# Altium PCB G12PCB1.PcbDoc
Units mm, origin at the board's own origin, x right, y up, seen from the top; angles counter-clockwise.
Board outline 41 x 76.01 mm, 2 copper layers (Top Layer, Bottom Layer); 30 components, 21 nets, 144 pads, 45 vias.
Unrouted connection lines stored in the file: 2.
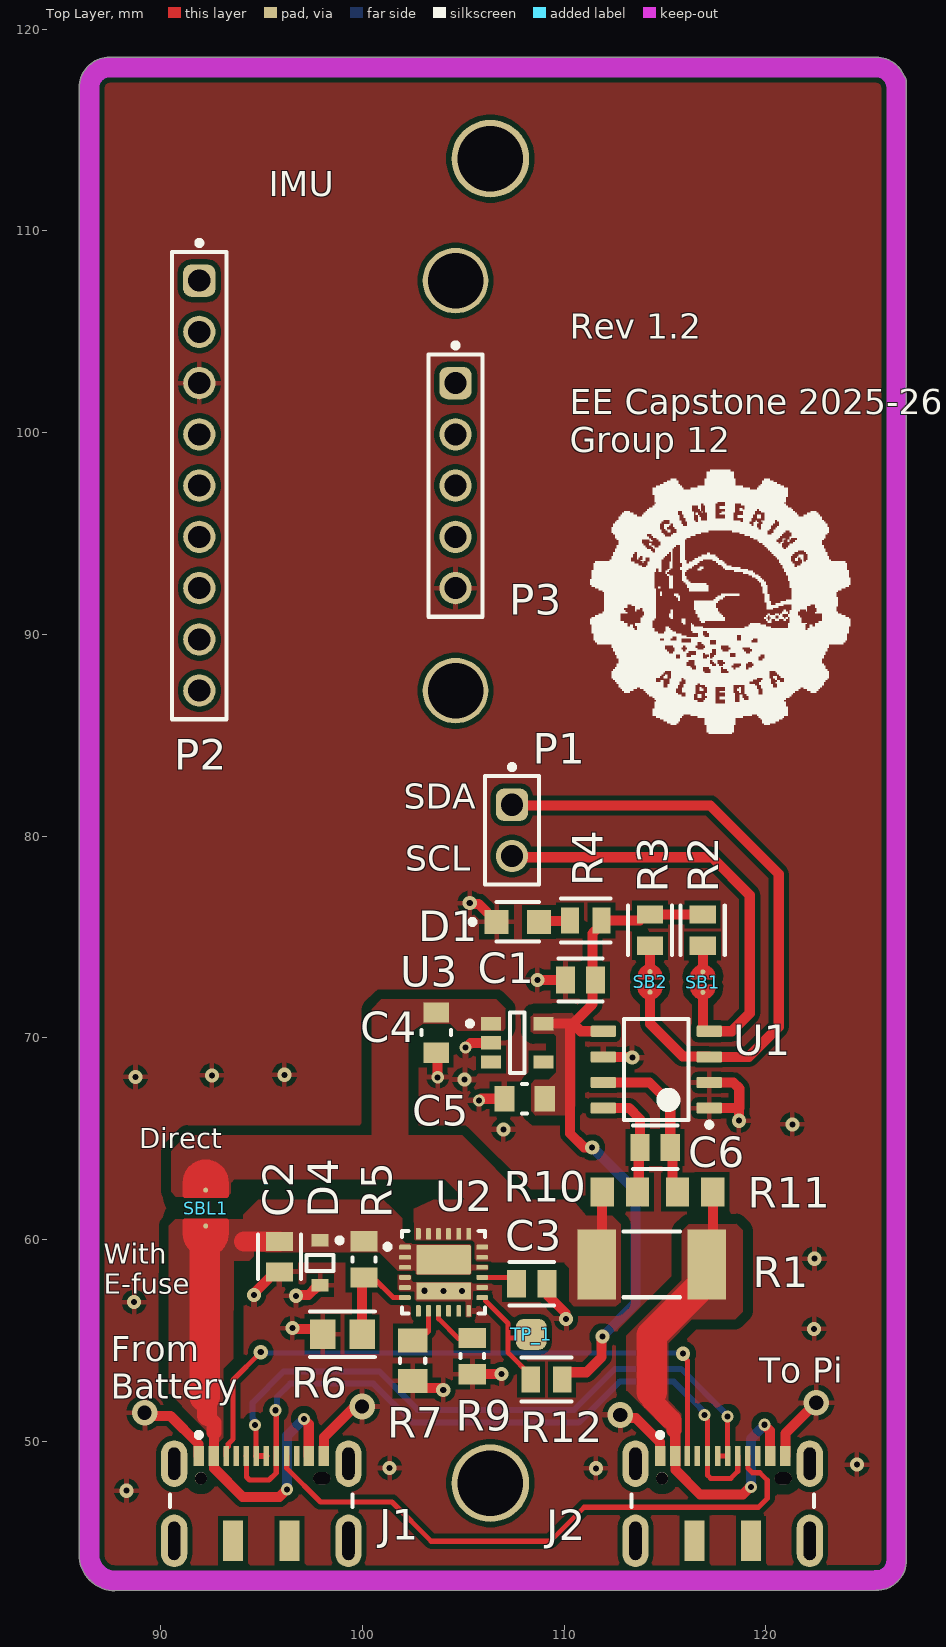
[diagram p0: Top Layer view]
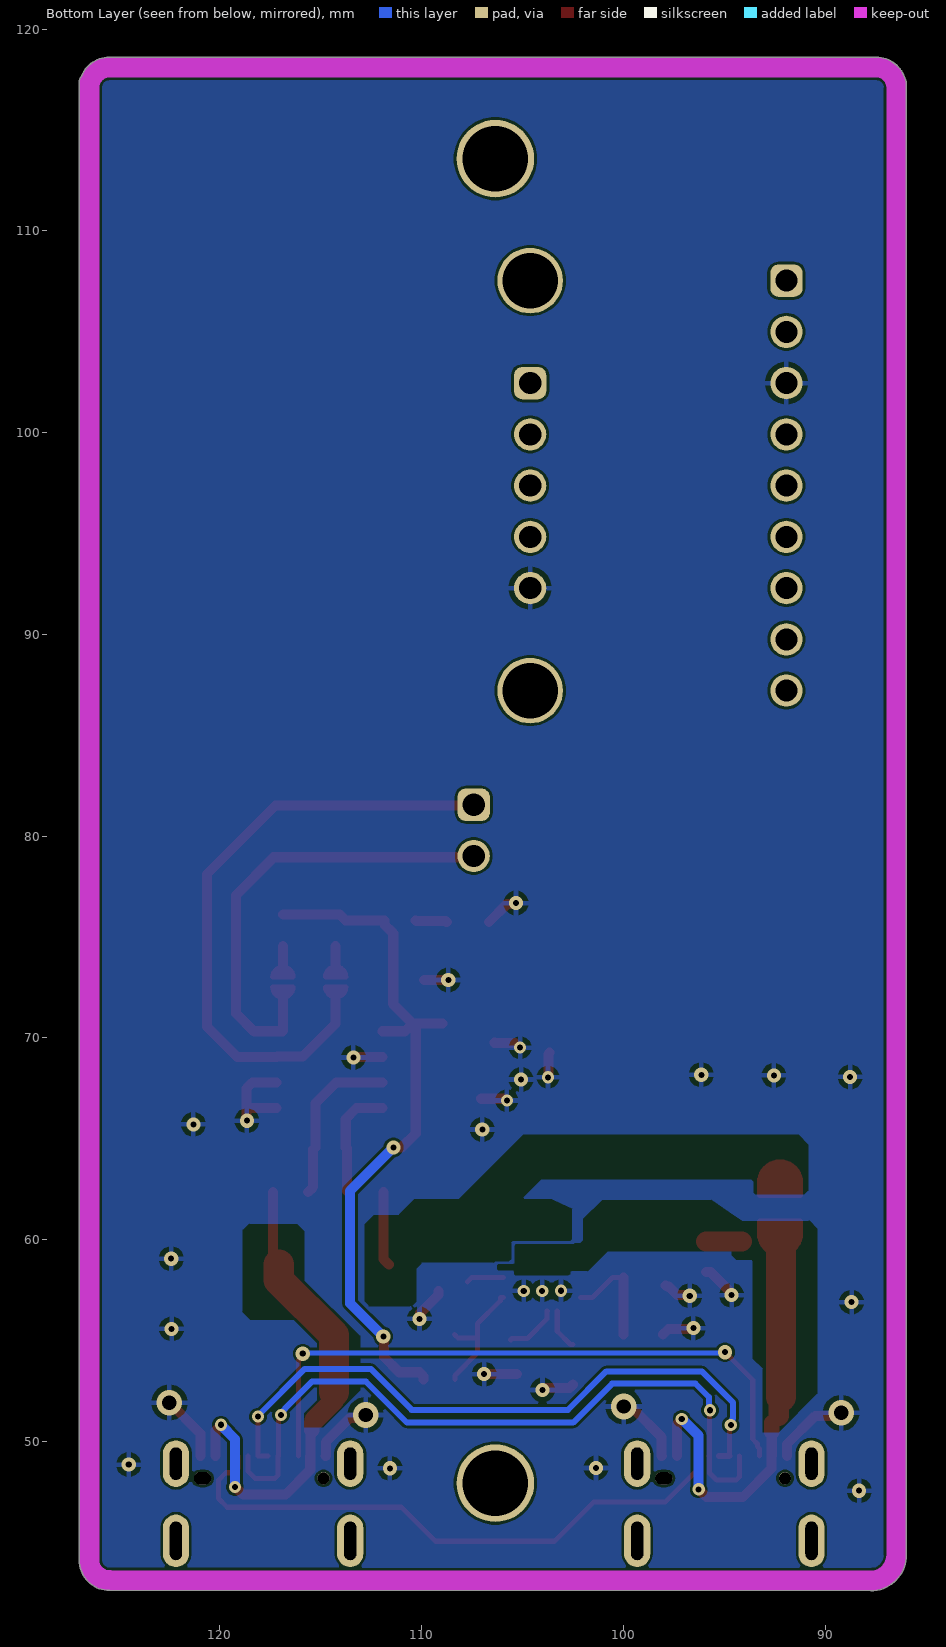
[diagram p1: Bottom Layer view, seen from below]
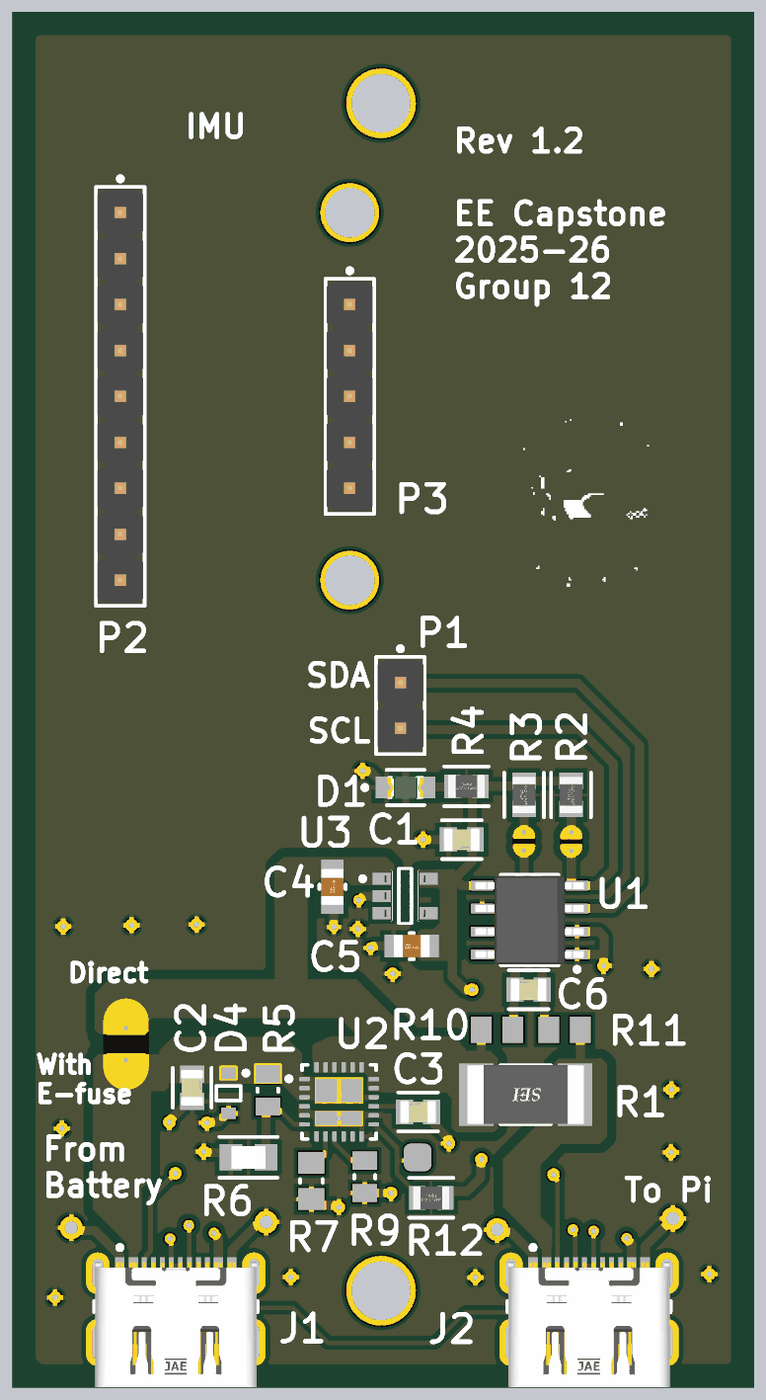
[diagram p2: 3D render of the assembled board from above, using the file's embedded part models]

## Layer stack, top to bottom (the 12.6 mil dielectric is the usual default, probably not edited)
Top Solder: solder mask 0.0102, Solder Resist, Dk 3.5
Top Layer: signal copper 0.0356
Dielectric 1: dielectric 0.32, FR-4, Dk 4.8
Bottom Layer: signal copper 0.0356
Bottom Solder: solder mask 0.0102, Solder Resist, Dk 3.5

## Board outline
85.969,44.367 85.969,117.105 cw(c87.469,117.105) 87.469,118.605 125.469,118.605 cw(c125.469,117.105) 126.853,117.684 cw(c126.469,117.363) 126.969,117.363 126.969,44.113 cw(c125.469,44.113) 125.469,42.613 87.739,42.597 cw(c87.739,44.367)

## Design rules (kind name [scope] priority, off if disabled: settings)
BoardOutlineClearance [All] p1: gap=0.5 ignorepadtopadclearanceinfootprint=FALSE
Clearance Clearance_8 [InComponent('SBL1') vs InNamedPolygon('GND_L01_P029')] p1: gap=1 ignorepadtopadclearanceinfootprint=FALSE
Clearance Clearance_7 [(HasFootprint('Solder Bridge (Large)')) vs InNet('GND')] p2: gap=0.75 ignorepadtopadclearanceinfootprint=FALSE
Clearance Clearance_6 [InNamedPolygon('+5_IN_L02_P000') vs InNamedPolygon('GND_L02_P028')] p3: gap=0.5 ignorepadtopadclearanceinfootprint=FALSE
Clearance Clearance_5 [InNamedPolygon('GND_L01_P029')] p4: gap=0.254 ignorepadtopadclearanceinfootprint=FALSE except(0.5: Poly-Poly Poly-Region Poly-Text Poly-Hole)
Clearance Clearance_4 [InNamedPolygon('NONET_L02_P027') vs IsNamedPolygon('GND_L01_P029')] p5: gap=0.5 ignorepadtopadclearanceinfootprint=FALSE
Clearance Clearance_3 [InNamedPolygon('GND_L01_P029')] p6: gap=0.2 ignorepadtopadclearanceinfootprint=FALSE
Clearance Clearance_2 [IsNamedPolygon('GND_L01_P029')] p7: gap=0.2 ignorepadtopadclearanceinfootprint=FALSE
Clearance Clearance_1 [All] p8: gap=0.127 ignorepadtopadclearanceinfootprint=TRUE
Clearance [All] p9 off: gap=0.2 ignorepadtopadclearanceinfootprint=FALSE
HoleSize HoleSize_1 [All] p1: absolutevalues=TRUE maxlimit=5 minlimit=0.15 maxpercent=80.000 minpercent=20.000
HoleSize [All] p2 off: absolutevalues=TRUE maxlimit=2.54 minlimit=0.025 maxpercent=80.000 minpercent=20.000
MinimumAnnularRing [All] p1: minimumring=0.1
MinimumSolderMaskSliver MinimumSolderMaskSliver_1 [All] p1: minsoldermaskwidth=0.2
MinimumSolderMaskSliver [All] p2: minsoldermaskwidth=0.254
PolygonConnect PolygonConnect_4 [All vs IsNamedPolygon('+5_IN_L02_P000')] p1: connectstyle=Relief reliefconductorwidth=0.254 reliefentries=4 polygonreliefangle="90 Angle" airgapwidth=0.254
PolygonConnect PolygonConnect_3 [IsNamedPolygon('GND_L01_P029')] p2: connectstyle=Relief reliefconductorwidth=0.254 reliefentries=4 polygonreliefangle="90 Angle" airgapwidth=0.254
PolygonConnect PolygonConnect_2 [All vs IsNamedPolygon('GND_L02_P028')] p3: connectstyle=Relief reliefconductorwidth=0.254 reliefentries=4 polygonreliefangle="90 Angle" airgapwidth=0.254
PolygonConnect "E-fuse In" [All vs IsNamedPolygon('+5_IN_L01_P006')] p4 off: thpad.connectstyle=NoConnect thpad.reliefconductorwidth=0.254 thpad.reliefentries=4 thpad.polygonreliefangle="90 Angle" thpad.airgapwidth=0.254 smdpad.connectstyle=NoConnect smdpad.reliefconductorwidth=0.254 smdpad.reliefentries=4 smdpad.polygonreliefangle="90 Angle" smdpad.airgapwidth=0.254 via.connectstyle=Relief via.reliefconductorwidth=0.254 via.reliefentries=4 via.polygonreliefangle="90 Angle" via.airgapwidth=0.254
PolygonConnect PolygonConnect_1 [All vs IsNamedPolygon('NONET_L01_P008')] p5 off: thpad.connectstyle=Direct thpad.reliefconductorwidth=0.254 thpad.reliefentries=4 thpad.polygonreliefangle="90 Angle" thpad.airgapwidth=0.254 smdpad.connectstyle=Direct smdpad.reliefconductorwidth=0.254 smdpad.reliefentries=4 smdpad.polygonreliefangle="90 Angle" smdpad.airgapwidth=0.254 via.connectstyle=Relief via.reliefconductorwidth=0.254 via.reliefentries=4 via.polygonreliefangle="90 Angle" via.airgapwidth=0.254
PolygonConnect [All] p6: connectstyle=Direct reliefconductorwidth=0.254 reliefentries=4 polygonreliefangle="90 Angle" airgapwidth=0.254
RoutingVias RoutingVias_2 [All] p1: holewidth=0.711 width=1.27 viastyle="Through Hole" minholewidth=0.15 minwidth=0.25 maxholewidth=0.711 maxwidth=1.27
RoutingVias RoutingVias_1 [All] p2: holewidth=0.711 width=1.27 viastyle="Through Hole" minholewidth=0.3 minwidth=0.6 maxholewidth=0.711 maxwidth=1.27
RoutingVias [All] p3: holewidth=0.711 width=1.27 viastyle="Through Hole" minholewidth=0.711 minwidth=1.27 maxholewidth=0.711 maxwidth=1.27
SilkToSolderMaskClearance [IsPad] p1: minsilkscreentomaskgap=0.2 clearancetoexposedcopper=TRUE
SolderMaskExpansion [All] p1: expansion=0.102 istentingtop=FALSE
SupplyNets "Schematic Supply Nets_4" [InNet('+3V3')] p1: voltage=0.000
SupplyNets "Schematic Supply Nets_2" [InNet('+5 OUT')] p2: voltage=0.000
SupplyNets "Schematic Supply Nets_3" [InNet('+5 IN')] p3: voltage=0.000
SupplyNets "Schematic Supply Nets_1" [InNet('+5')] p4: voltage=0.000
SupplyNets "Schematic Supply Nets" [InNet('GND')] p5: voltage=0.000
Width Width_1 [All] p1: maxlimit=2 minlimit=0.127 preferedwidth=0.3
Width [All] p2 off: maxlimit=1 minlimit=0.254 preferedwidth=0.254 minimp=50.000000 maximp=50.000000 favimp=50.000000
27 further rules are at their usual default settings.

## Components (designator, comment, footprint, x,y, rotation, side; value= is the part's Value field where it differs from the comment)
C1 "C0805C104K5RACTU" FP-C0805C-DN-MFG 110.815,72.87 r180 top value="0.10 μF"
C2 "C0805C104K5RACTU" FP-C0805C-DN-MFG 95.892,59.153 r270 top value="0.10 μF"
C3 "C0805C223J1RACAUTO" FP-C0805C-DN-MFG 108.398,57.817 r0 top value="22,000 pF"
C4 "08051C105K4T2A" FP-0805-L_2_01_0_2-W_1_25-MFG 103.659,70.261 r270 top
C5 "08051C105K4T2A" FP-0805-L_2_01_0_2-W_1_25-MFG 108.042,66.982 r180 top
C6 "C0805C104K5RACTU" FP-C0805C-DN-MFG 114.511,64.572 r0 top value="0.10 μF"
D1 "APHCM2012CGCK-F01" FP-APHCM2012CGCK-F01-MFG 107.705,75.749 r0 top
D4 "SD05T1G" ONSC-SOD-323-2-477-02_G_V 97.907,58.849 r270 top
J1 "DX07S016JA1R1500" FP-DX07S016JA1R1500-MFG 94.994,46.07 r0 top
J2 "DX07S016JA1R1500" FP-DX07S016JA1R1500-MFG 117.858,46.07 r0 top
P1 "61300211121" 61300211121 107.418,80.284 r270 top
P2 "61300911121" 61300911121 91.919,97.373 r270 top
P3 "61300511121" 61300511121 104.619,97.373 r270 top
R1 "CSRF2512FT10L0" FP-CSRF2512-IPC_B 114.352,58.769 r180 top
R2 "CRGCQ0805F4K7" FP-CRGCQ0805-IPC_C 116.864,75.339 r90 top value=4.7KΩ
R3 "CRGCQ0805F4K7" FP-CRGCQ0805-IPC_C 114.259,75.339 r90 top value=4.7KΩ
R4 "CRGCQ0805F4K7" FP-CRGCQ0805-IPC_C 111.074,75.817 r0 top value=4.7KΩ
R5 "RV0805FR-071ML" RESC2013X60X35NL10T20 100.088,59.018 r90 top
R6 "CR0805-FX-4323ELF" FP-CR0805-IPC_A 99.01,55.309 r0 top
R7 "RC0805FR-07357RL" RESC2013X60X35ML10T20 102.493,53.998 r90 top
R9 "RC0805FR-07316RL" RESC2013X60X35NL10T20 105.446,54.23 r270 top
R10 "ERJ-6ENF10R0V" RESC2013X70X40NL20T20 112.763,62.358 r180 top
R11 "ERJ-6ENF10R0V" RESC2013X70X40NL20T20 116.497,62.358 r0 top
R12 "CRGCQ0805J10K" FP-CRGCQ0805-IPC_C 109.128,53.069 r0 top value=10KΩ
SB1 "Solder Bridge" "Solder Bridge"#1 116.877,72.764 r270 top
SB2 "Solder Bridge" "Solder Bridge"#2 114.259,72.775 r270 top
SBL1 "Solder Bridge (Large)" "Solder Bridge (Large)" 92.236,61.564 r270 top
TP_1 "TP_1" "Test Pad" 108.375,55.303 r90 top
U1 "INA219AIDR" D0008A_L 114.57,68.425 r180 top
U3 "MIC5504-3.3YM5-TR" FP-SOT23-5LD-PL-1-MFG 107.679,69.757 r0 top

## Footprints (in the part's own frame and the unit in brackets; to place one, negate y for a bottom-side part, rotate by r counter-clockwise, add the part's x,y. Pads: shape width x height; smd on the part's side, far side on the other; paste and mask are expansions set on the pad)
61300211121 [mm] "Pin Header, pitch 2.54 mm, THT, Vertical, single row, 2p"
  rrect50% 1.6x1.6 hole 1.1: 1(-1.27,0)
  round 1.6 hole 1.1: 2(1.27,0)
  silkscreen extent -3.26,-1.35 2.69,1.35, body extent -2.54,-1.27 2.54,1.27, height 8.57
61300511121 [mm] "Pin Header, pitch 2.54 mm, THT, Vertical, single row, 5p"
  rrect50% 1.6x1.6 hole 1.1: 1(-5.08,0)
  round 1.6 hole 1.1: 2(-2.54,0) 3(0,0) 4(2.54,0) 5(5.08,0)
  silkscreen extent -7.07,-1.35 6.5,1.35, body extent -6.35,-1.27 6.35,1.27, height 8.57
61300911121 [mm] "Pin Header, pitch 2.54 mm, THT, Vertical, single row, 9p"
  rrect50% 1.6x1.6 hole 1.1: 1(-10.16,0)
  round 1.6 hole 1.1: 2(-7.62,0) 3(-5.08,0) 4(-2.54,0) 5(0,0) 6(2.54,0) 7(5.08,0) 8(7.62,0) 9(10.16,0)
  silkscreen extent -12.15,-1.35 11.58,1.35, body extent -11.43,-1.27 11.43,1.27, height 8.57
D0008A_L [mm] "SOIC, 8-Leads, Body 5x4mm, Pitch 1.27mm, IPC High Density"
  rrect18% 1.25x0.55 smd: 1(-2.625,1.905) 2(-2.625,0.635) 3(-2.625,-0.635) 4(-2.625,-1.905) 5(2.625,-1.905) 6(2.625,-0.635) 7(2.625,0.635) 8(2.625,1.905)
  silkscreen extent -2.75,-2.5 1.6,2.85, body extent -3,-2.45 3,2.45, height 1.63
FP-0805-L_2_01_0_2-W_1_25-MFG [mm]
  rect 1x1.25 smd paste+0 mask+0: 1(-1,0) 2(1,0)
  silkscreen extent -0.13,-0.72 0.13,0.72, body extent -1.6,-0.82 1.6,0.82, height 0.25
FP-APHCM2012CGCK-F01-MFG [mm]
  rect 1.2x1.2 smd paste+0 mask+0: 1(-1.05,0) 2(1.05,0)
  silkscreen extent -2.37,-0.97 1.05,0.97, body extent -1.75,-0.77 1.75,0.77, height 0.25
FP-C0805C-DN-MFG [mm]
  rect 0.95x1.35 smd paste+0 mask+0: 1(-0.75,0) 2(0.75,0)
  silkscreen extent -1.1,-1.07 1.1,1.07, body extent -1.4,-0.85 1.4,0.85, height 0.25
FP-CR0805-IPC_A [mm]
  rect 1.258x1.462 smd paste+0 mask+0: 1(-0.977,0) 2(0.977,0)
  silkscreen extent -1.61,-1.13 1.61,1.13, body extent -2.11,-1.23 2.11,1.23, height 0.25
FP-CRGCQ0805-IPC_C [mm]
  rect 0.906x1.31 smd paste+0 mask+0: 1(-0.776,0) 2(0.776,0)
  silkscreen extent -1.23,-1.1 1.23,1.1, body extent -1.33,-0.8 1.33,0.8, height 0.25
FP-CSRF2512-IPC_B [mm]
  rect 1.905x3.456 smd paste+0 mask+0: 1(-2.726,0) 2(2.726,0)
  silkscreen extent -1.4,-1.63 1.4,1.63, body extent -3.93,-1.98 3.93,1.98, height 0.25
FP-DX07S016JA1R1500-MFG [mm]
  rrect100% 1.3x2.3 hole 1.6 slot 0.6 at 0 deg paste-2539.97 mask+0: 1(-4.32,2.825) 2(4.32,2.825)
  rrect100% 1.3x2.6 hole 1.9 slot 0.6 at 0 deg paste-2539.97 mask+0: 3(-4.32,-1) 6(4.32,-1)
  rect 1x2 smd paste+0 mask+0: 4(-1.4,-1) 5(1.4,-1)
  rect 0.52x1 smd paste+0 mask+0: A1/B12(-3.1,3.2) A4/B9(-2.35,3.2) A12/B1(3.1,3.2) B4/A9(2.35,3.2)
  rect 0.27x1 smd paste+0 mask+0: A5(-1.75,3.2) A6(-0.25,3.2) A7(0.75,3.2) A8(1.75,3.2) B5(1.25,3.2) B6(0.25,3.2) B7(-0.75,3.2) B8(-1.25,3.2)
  round 0.6 hole 0.6 unplated paste-2539.97 mask+0: ""(-3,2.1)
  rrect100% 0.85x0.6 hole 0.6 slot 0.85 at 0 deg unplated paste-2539.97 mask+0: ""(3,2.1)
  silkscreen extent -4.52,0.67 4.52,4.37, body extent -5.07,-3.75 5.07,4.08, height 0.25
FP-SOT23-5LD-PL-1-MFG [mm]
  rect 1x0.66 smd paste+0 mask+0: 1(-1.3,0.95) 2(-1.3,0) 3(-1.3,-0.95) 4(1.3,-0.95) 5(1.3,0.95)
  silkscreen extent -2.47,-1.5 0.35,1.5, body extent -1.9,-1.6 1.9,1.6, height 0.25
ONSC-SOD-323-2-477-02_G_V [mm] "SOD, 2-Leads, Body 1.7x1.25mm"
  rect 0.63x0.83 smd: 1(-1.115,0) 2(1.115,0)
  silkscreen extent -1.24,-0.67 0.4,1.09, body extent -0.85,-0.63 0.85,0.63, height 1.06
RESC2013X60X35ML10T20 [mm] "Chip Resistor, 2-Leads, Body 2.00x1.25mm, IPC Low Density"
  rect 1.2x1.45 smd: 1(-1,0) 2(1,0)
  silkscreen extent -0.1,-0.63 0.1,0.63, body extent -1.05,-0.67 1.05,0.67, height 0.6
RESC2013X60X35NL10T20 [mm] "Chip Resistor, 2-Leads, Body 2.00x1.25mm, IPC Medium Density"
  rect 1x1.35 smd: 1(-0.9,0) 2(0.9,0)
  silkscreen extent -0.1,-0.58 0.1,0.58, body extent -1.05,-0.67 1.05,0.67, height 0.6
RESC2013X70X40NL20T20 [mm] "Chip Resistor, 2-Leads, Body 2.00x1.25mm, IPC Medium Density"
  rect 1.15x1.45 smd: 1(-0.875,0) 2(0.875,0)
  body extent -1.1,-0.72 1.1,0.72, height 0.7
"Solder Bridge"#1 [mm]
  round 0.25 smd mask+0: 1(0.508,0) 2(-0.508,0)
  Top Layer region: 0.254,0.5 0.449,0.456 0.754,0.181 0.754,-0.164 0.519,-0.399 0.449,-0.469 0.254,-0.5
  Top Layer region: -0.254,-0.5 -0.449,-0.456 -0.754,-0.181 -0.754,0.164 -0.519,0.399 -0.449,0.469 -0.254,0.5
  Top Layer lines w0.254: 0.254,-0.5 ccw(c0.254,0) 0.254,0.5 0.254,-0.5 ; -0.254,-0.5 cw(c-0.254,0) -0.254,0.5 -0.254,-0.5
"Solder Bridge"#2 [mm]
  round 0.25 smd mask+0: 1(0.508,0) 2(-0.508,0)
  Top Layer region: 0.254,0.5 0.449,0.456 0.754,0.181 0.754,-0.164 0.519,-0.399 0.449,-0.469 0.254,-0.5
  Top Layer region: -0.254,-0.5 -0.449,-0.456 -0.754,-0.181 -0.754,0.164 -0.519,0.399 -0.449,0.469 -0.254,0.5
  Top Layer lines w0.254: 0.254,-0.5 ccw(c0.254,0) 0.754,0.009 ccw(c0.254,0) 0.254,0.5 0.254,-0.5 ; -0.254,-0.5 cw(c-0.254,0) -0.254,0.5 -0.254,-0.5
"Solder Bridge (Large)" [mm]
  round 0.25 smd mask+0: 1(0.889,0) 2(-0.889,0)
  Top Layer region: 0.635,1.016 1.651,1.016 2.286,0.381 2.286,-0.381 1.651,-1.016 0.635,-1.016
  Top Layer region: -0.635,-1.016 -1.651,-1.016 -2.286,-0.381 -2.286,0.381 -1.651,1.016 -0.635,1.016
  Top Layer lines w0.254: 0.635,-1.016 1.27,-1.016 ccw(c1.27,0) 2.285,-0.046 ccw(c1.27,0) 2.286,0 ccw(c1.27,0) 1.27,1.016 0.635,1.016 ; -0.635,-1.016 -1.27,-1.016 cw(c-1.27,0) -2.286,0 cw(c-1.27,0) -1.27,1.016 -0.635,1.016 ; 0.635,-1 0.635,1 ; -0.635,-1 -0.635,1
"Test Pad" [mil]
  rrect50% 60x60 smd: TP1(0,0)

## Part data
C1 C2 C6: library part CMP-2007-00279-2, "CAP CER 0.1UF 50V X7R 0805", Capacitance="0.10 μF", Manufacturer=KEMET, Package=C0805C-DN, Temperature="-55°C to +125°C", Temperature Characteristic=X7R, Temperature Coefficient=30ppm/°C, Temperature Range High=+125°C, Temperature Range Low=-55°C, Tolerance=0.1, Voltage Rating="50 V"
C3: library part CMP-03020-025363-1, "C0805 22,000 pF X7R 30ppm/°C 5.00% 100 V", Capacitance="22,000 pF", Manufacturer=KEMET, Package=C0805C-DN, Temperature="-55°C to +125°C", Temperature Characteristic=X7R, Temperature Coefficient=30ppm/°C, Temperature Range High=+125°C, Temperature Range Low=-55°C, Tolerance=0.05, Voltage Rating="100 V"
C4 C5: library part CMP-07738-122049624-1, "08051C105K4T2A Cap Ceramic 1uF 100V X7R 10% Pad SMD 0805 125C Automotive T/R", Capacitance=1µF, Case/Package=0805, Dielectric=X7R, Max Operating Temperature=125°C, Min Operating Temperature=-55°C, Tolerance=10%, Voltage Rating=100V
D1: library part CMP-44529-000062-1, "LED GREEN CLEAR CHIP SMD", Case Code (Imperial)=0805, Case Code (Metric)=2012, Color=Green, Forward Current=20mA, Forward Voltage=2.1V, Lens Color=Clear, Max Operating Temperature=85°C, Min Operating Temperature=-40°C, Package Quantity=1
D4: library part CMP-1061-00629-1, "Transient Voltage Suppressor Diode, for ESD Protection, 2-Pin SOD-323, Pb-Free, Tape and Reel", Manufacturer="On Semiconductor"
J1 J2: library part CMP-19038-000003-1, "CONN RCP USB2.0 TYP C 24P SMD RA"
P1: library part CMP-1712-00002-7, "THT Vertical Pin Header WR-PHD, Pitch 2.54 mm, Single Row, 2 pins", Color=Black, Contact Resistance=20mΩ, Current Rating=3A, Max Operating Temperature=105°C, Min Operating Temperature=-40°C, Operating Supply Voltage=250V
P2: library part CMP-1502-01080-3, Color=Black, Contact Resistance=20mΩ, Current Rating=3A, Operating Supply Voltage=250V
P3: library part CMP-1502-01068-4, "THT Vertical Pin Header WR-PHD, Pitch 2.54 mm, Single Row, 5 pins", Color=Black, Contact Resistance=20mΩ, Current Rating=3A, Max Operating Temperature=105°C, Min Operating Temperature=-40°C, Operating Supply Voltage=250V
R1: library part CMP-26527-001250-1, "Foil on Ceramic Current Sensing Chip Resistor 10mΩ ±1% 2W 2512 AEC Qualified", Case Code (Imperial)=2512, Case Code (Metric)=6432, Max Operating Temperature=170°C, Max Power Dissipation=2W, Min Operating Temperature=-55°C, Resistance=10mR, Resistor Type="Metal Foil", Temperature Coefficient=100ppm/°C, Tolerance=1%
R2 R3 R4: library part CMP-03211-010668-1, "CRGCQ0805 4.7KΩ 0.125W ±100ppm/°C 1% 150V", Ambient Temperature Range High=+70°C, Manufacturer="TE Connectivity", Package=CRGCQ0805, Power Rating=0.125W, Resistance=4.7KΩ, Temperature="-55°C to +155°C", Temperature Coefficient=±100ppm/°C, Temperature Range High=+155°C, Temperature Range Low=-55°C, Tolerance=0.01, Voltage Rating=150V
R5: library part CMP-2001-01791-1, Manufacturer=Yageo
R6: library part CMP-07231-005639-1, "Thick Film Chip Resistors 0805 432kΩ 0.125W 1% 100ppm/°C", Case Code (Imperial)=0805, Case Code (Metric)=2012, Max Operating Temperature=155°C, Min Operating Temperature=-55°C, Package Quantity=5000, Power Rating=125mW, Resistance=432kR, Temperature Coefficient=100ppm/°C, Tolerance=1%, Voltage Rating=150V
R7: library part CMP-2001-01096-1, Manufacturer=Yageo
R9: library part CMP-2001-01081-1, Manufacturer=Yageo
R10 R11: library part CMP-1013-00284-2, Manufacturer=Panasonic
R12: library part CMP-03211-002989-1, "CRGCQ 0805 10K 5%", Ambient Temperature Range High=+70°C, Manufacturer="TE Connectivity", Package=CRGCQ0805, Power Rating=0.125W, Resistance=10KΩ, Temperature="-55°C to +155°C", Temperature Coefficient=±100ppm/°C, Temperature Range High=+155°C, Temperature Range Low=-55°C, Tolerance=0.05, Voltage Rating=150V
TP_1: library part "Test Pad"
U1: library part CMP-0704-00003-2, "Zero-Drift, Bi-Directional Current / Power Monitor, 3 to 5.5 V, -40 to 125 degC, 8-pin SOIC (D8), Green (RoHS & no Sb/Br)", Manufacturer="Texas Instruments", Quiescent Current (+/-)(Typ)(mA)=0.7, Rating=Catalog
U3: library part CMP-2000-07604-2, "IC REG LINEAR 3.3V 300MA SOT23-5", Case/Package=SOT-23-5, Dropout Voltage=380mV, Max Input Voltage=5.5V, Max Operating Temperature=125°C, Max Output Current=300mA, Min Input Voltage=2.5V, Min Operating Temperature=-40°C, Nominal Output Voltage=3.3V, Operating Supply Current=42uA, Power Supply Rejection Ratio (PSRR)=60dB, Quiescent Current=38uA

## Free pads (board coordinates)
  rrect42% 0.575x0.24 smd paste+0 mask+0: 1(102.113,59.628) 2(102.113,59.128) 3(102.113,58.628) 4(102.113,58.128) 5(102.113,57.628) 6(102.113,57.128) 13(105.938,57.128) 14(105.938,57.628) 15(105.938,58.128) 16(105.938,58.628) 17(105.938,59.128) 18(105.938,59.628)
  rrect42% 0.24x0.575 smd paste+0 mask+0: 7(102.776,56.466) 8(103.276,56.466) 9(103.776,56.466) 10(104.276,56.466) 11(104.776,56.466) 12(105.276,56.466) 19(105.276,60.291) 20(104.776,60.291) 21(104.276,60.291) 22(103.776,60.291) 23(103.276,60.291) 24(102.776,60.291)
  rrect7% 2.7x1.45 smd paste-1000 mask+0: 25(104.026,59.003)
  rrect12% 2.7x0.85 smd paste-1000 mask+0: 26(104.026,57.453)
  round 3.25 hole 2.75: MH(104.619,107.533) MH(104.619,87.213)
  round 3.85 hole 3.25: MH(106.347,47.929) MH(106.347,113.579)

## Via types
v1: diameter 0.7, hole 0.3, Top Layer to Bottom Layer, 27 vias
v2: diameter 0.6, hole 0.3, Top Layer to Bottom Layer, 14 vias
v3: diameter 1.27, hole 0.711, Top Layer to Bottom Layer, 4 vias

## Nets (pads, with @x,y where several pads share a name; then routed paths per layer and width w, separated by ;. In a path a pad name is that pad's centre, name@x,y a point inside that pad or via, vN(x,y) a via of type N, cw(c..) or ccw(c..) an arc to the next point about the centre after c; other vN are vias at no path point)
+3V3: C1.1 C5.1 R2.2 R3.2 R4.2 R12.2 U1.5 U3.5 | length 35.3
  Top Layer w0.5: U3.5 110.442,70.707 ; R12.2 109.904,53.222 110.107,53.425 111.107,53.425 111.862,54.18 111.862,55.157 v1(111.9,55.195) ; v1(111.394,64.572) 110.982,64.572 110.289,65.265 110.289,70.554 110.442,70.707 ; U1.5 110.819,70.33 110.442,70.707 ; R2.2 R3.2 114.057,76.115 113.764,75.822 111.845,75.822 111.845,75.62 111.405,75.18 111.405,72.775 111.405,71.67 110.442,70.707
  Bottom Layer w0.5: v1(111.394,64.572) 113.546,62.42 113.546,56.841 v1(111.9,55.195)
+5: J2.A4/B9 J2.B4/A9 R1.1 R11.2 | length 24.9
  Top Layer w0.5: 115.443,50.546 115.508,50.481 J2.A4/B9 115.518,49.26 115.518,48.593 116.74,47.371 118.859,47.371 119.231,47.743 v2(119.258,47.743) ; R1.1 117.372,59.063 R11.2 ; v2(119.938,50.825) 119.938,50.798 120.208,50.528 J2.B4/A9
  Top Layer w0.75: 115.316,51.054 115.443,50.927 115.443,50.546
  Top Layer w1: 114.339,52.446 114.339,52.031 115.316,51.054
  Top Layer w1.5: 114.339,52.446 114.339,55.255 117.078,57.993 R1.1
  Bottom Layer w0.5: v2(119.258,47.743) 119.258,50.118 119.938,50.798 v2(119.938,50.825)
"+5 IN": C2.1 D4.1 J1.A4/B9 J1.B4/A9 pad.1 pad.2 pad.3 pad.16 pad.25 R5.2 SBL1.1 | length 23.4
  Top Layer w0.5: 92.644,50.447 J1.A4/B9 92.654,49.26 92.654,48.662 94.072,47.244 95.885,47.244 v2(96.266,47.625) ; v2(97.105,51.119) 97.105,51.092 97.344,50.853 J1.B4/A9
  Top Layer w0.75: 92.302,51.269 92.644,50.927 92.644,50.447
  Top Layer w1: 92.19,52.217 92.302,52.105 92.302,51.269 ; 94.131,59.903 C2.1
  Top Layer w1.5: 92.19,52.217 92.19,59.279 92.19,59.913
  Bottom Layer w0.5: v2(96.266,47.625) 96.266,50.28 v2(97.105,51.119)
"+5 OUT": C4.1 pad.17 pad.18 pad.19 pad.20 pad.21 pad.22 pad.23 pad.24 R1.2 R10.2 SBL1.2 U3.1 | length 3.9
  Top Layer w0.5: R1.2 111.888,59.031 R10.2
  Top Layer w0.75: 92.236,62.834 92.236,63.062
CC1: J1.A5 J2.A5 | length 32
  Top Layer w0.254: J1.A5 93.244,49.635 93.355,49.746 93.355,49.875 93.589,50.109 93.589,53.043 v1(94.966,54.42) ; v1(115.892,54.346) 115.892,54.225 116.108,54.009 J2.A5
  Bottom Layer w0.254: v1(94.966,54.42) 95.003,54.383 115.855,54.383 v1(115.892,54.346)
CC2: J1.B5 J2.B5 | length 29.5
  Top Layer w0.254: J1.B5 96.252,49.262 96.252,48.665 97.927,46.99 101.473,46.99 103.412,45.051 109.313,45.051 110.998,46.736 119.634,46.736 120.07,47.172 120.07,48.075 119.703,48.442 119.338,48.442 119.116,48.665 119.116,49.262 J2.B5
D+: J1.A6 J1.B6 J2.A6 J2.B6 | length 32.5
  Top Layer w0.254: v2(94.676,50.808) 94.736,50.748 94.736,49.278 J1.A6@94.743,49.271 ; J2.A6 J2.B6 v2(118.108,51.227)
  Top Layer w0.3: J1.A6@94.743,49.271 J1.A6 J1.B6 J1.B6@95.247,49.273
  Bottom Layer w0.3: v2(94.676,50.808) 94.619,50.865 94.619,51.078 94.564,51.132 94.564,51.925 96.106,53.467 100.838,53.467 102.743,51.562 110.49,51.562 112.522,53.594 115.793,53.594 118.108,51.279 v2(118.108,51.227)
D-: J1.A7 J1.B7 J2.A7 J2.B7 | length 35.9
  Top Layer w0.254: J1.B7 94.252,49.262 94.252,48.23 94.401,48.081 95.379,48.081 95.736,48.438 95.736,49.262 J1.A7 95.736,49.278 95.736,51.512 v2(95.705,51.543) ; v2(116.967,51.308) 116.967,51.187 117.1,51.054 117.1,49.278 117.116,49.262 117.116,48.316 117.265,48.167 118.26,48.167 118.608,48.515 J2.A7
  Bottom Layer w0.3: v2(95.705,51.543) 95.762,51.6 95.762,52.201 96.426,52.865 100.551,52.865 102.489,50.927 110.723,50.927 112.755,52.959 115.443,52.959 116.767,51.635 116.767,51.616 116.967,51.416 v2(116.967,51.308)
GND: C1.2 C2.2 C3.2 C4.2 C5.2 D1.1 D4.2 J1.A1/B12 J1.A12/B1 J2.A1/B12 J2.A12/B1 P2.3 P3.5 pad.4 pad.5 pad.12 pad.14 pad.26 R6.1 R7.1 R9.2 U1.1 U1.2 U1.6 U3.2 | length 36.8
  Top Layer w0.5: v3(89.206,51.412) 89.353,51.265 90.484,51.265 91.884,49.865 91.884,49.28 J1.A1/B12 ; P2.3@91.896,102.477 P2.3 ; v1(94.632,57.247) 94.632,57.343 95.692,58.403 C2.2 ; v1(96.533,55.613) 96.571,55.575 97.767,55.575 R6.1 ; v1(96.711,57.217) 96.749,57.255 97.328,57.255 97.742,57.669 97.842,57.669 D4.2 ; J1.A12/B1 98.104,49.28 98.104,50.21 99.474,51.58 99.84,51.58 v3(99.987,51.727) ; R7.1@102.502,52.807 102.661,52.648 103.857,52.648 103.957,52.548 v1(104.011,52.548) ; C4.2 103.717,69.203 103.717,68.065 v2(103.736,68.046) ; P3.5@104.619,92.297 P3.5@104.629,92.307 ; v2(105.116,69.519) 105.143,69.519 105.372,69.748 106.37,69.748 U3.2 ; R9.2@105.266,53.331 v1(106.901,53.331) ; v1(105.324,76.68) 105.362,76.642 105.762,76.642 D1.1 ; v2(105.773,66.894) 105.8,66.894 105.888,66.982 C5.2 ; v1(108.677,72.87) C1.2@109.889,72.87 ; C3.2@109.172,57.453 109.172,57.253 110.066,56.359 110.066,56.112 v1(110.104,56.074) ; U1.6 111.96,69.045 113.366,69.045 v1(113.381,69.03) ; v3(112.776,51.308) 112.923,51.161 113.555,51.161 114.748,49.968 114.748,49.28 J2.A1/B12 ; U1.1 118.672,66.52 ; U1.2 118.389,67.79 118.682,67.497 118.682,66.53 118.672,66.52 ; v1@118.669,65.913 118.672,65.916 118.672,66.52 ; J2.A12/B1 120.968,49.28 120.968,50.39 v3(122.5,51.922)
  other v1: 88.312,47.556 111.573,48.666 101.355,48.683 124.515,48.849 122.391,55.577 88.689,56.902 122.411,59.055 106.993,65.46 121.314,65.714 118.663,65.894 105.068,67.939 88.759,68.064 92.542,68.139 96.137,68.171
  other v2: 103.089,57.466 104.023,57.46 104.938,57.46
NetC3_1: C3.1 pad.15 | length 1.9
  Top Layer w0.254: pad.15 107.51,58.128 C3.1@107.729,57.909
NetC6_1: C6.1 R10.1 U1.8 | length 5.7
  Top Layer w0.5: U1.8 113.225,66.52 113.761,65.985 C6.1 113.699,64.51 113.699,62.419 R10.1
NetC6_2: C6.2 R11.1 U1.7 | length 8.3
  Top Layer w0.5: U1.7 114.231,67.79 115.261,66.76 C6.2 115.378,64.455 115.378,62.602 R11.1
NetD1_2: D1.2 R4.1 | length 1.6
  Top Layer w0.5: D1.2 108.791,75.786 110.257,75.786 R4.1@110.293,75.822
NetR2_1: R2.1 SB1.2 | length 1.3
  Top Layer w0.5: R2.1 116.877,74.55 SB1.2
NetR3_1: R3.1 SB2.2 | length 1.3
  Top Layer w0.5: SB2.2 R3.1
NetR5_1: pad.6 R5.1 R6.2 | length 5.4
  Top Layer w0.254: R5.1@99.987,58.128 100.534,58.128 101.534,57.128 pad.6
  Top Layer w0.5: R6.2 R5.1@99.987,58.128
NetR7_2: pad.8 R7.2 | length 2.1
  Top Layer w0.254: R7.2@102.502,54.807 102.627,54.807 103.276,55.455 pad.8
NetR9_1: pad.9 R9.1 | length 2.6
  Top Layer w0.254: pad.9 103.783,56.459 103.783,56.079 104.756,55.106 105.518,55.106 R9.1@105.585,55.039
NetR12_1: pad.13 R12.1 TP_1.TP1 | length 6.4
  Top Layer w0.254: pad.13 106.092,57.128 106.099,57.121 106.099,56.968 107.227,55.839 107.227,55.117 ; R12.1 108.352,53.271 107.227,54.396 107.227,55.117 ; TP_1.TP1 108.189,55.117 107.227,55.117
SCL: P1.2 SB1.1 U1.4 | length 23
  Top Layer w0.5: P1.2@107.418,78.953 117.327,78.953 119.204,77.076 119.204,71.219 118.315,70.33 U1.4 116.902,70.33 116.877,70.355 SB1.1
SDA: P1.1 SB2.1 U1.3 | length 31.4
  Top Layer w0.5: P1.1@107.418,81.519 117.244,81.519 120.64,78.123 120.64,70.546 119.154,69.06 U1.3 117.17,69.085 115.876,69.085 114.268,70.693 114.268,72.021 SB2.1@114.268,72.267
pads on no net: J1. J1.1 J1.2 J1.3 J1.4 J1.5 J1.6 J1.A8 J1.B8 J2. J2.1 J2.2 J2.3 J2.4 J2.5 J2.6 J2.A8 J2.B8 P2.1 P2.2 P2.4 P2.5 P2.6 P2.7 P2.8 P2.9 P3.1 P3.2 P3.3 P3.4 U3.3 U3.4

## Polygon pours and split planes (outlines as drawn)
GND on Top Layer "GND_L01_P029" (solid, pour order 29): 87.893,43.663 cw(c87.893,44.687) 87.169,43.963 cw(c87.411,44.205) 87.069,44.205 87.069,117.039 cw(c88.093,117.039) 87.369,117.763 cw(c87.611,117.522) 87.611,117.863 125.369,117.863 cw(c125.369,117.139) 125.881,117.651 125.969,117.563 cw(c125.728,117.322) 126.069,117.322 126.069,44.263 cw(c125.345,44.263) 125.857,43.751 125.769,43.663 125.269,43.663
"+5 OUT" on Top Layer "+5_OUT_L01_P016" (solid, pour order 16): 100.518,64.062 100.466,64.114 100.458,71.421 100.94,71.903 106.649,71.903 107.106,71.445 107.092,71.43 107.092,70.474 106.976,70.358 104.702,70.358 104.349,70.711 103.013,70.711 102.275,70.193 102.275,64.062
"+5 OUT" on Top Layer "+5_OUT_L01_P005" (solid, pour order 5): 91.155,62.118 91.151,62.122 90.759,62.122 90.759,62.132 90.518,62.373 90.518,64.385 90.684,64.546 91.317,65.179 91.326,65.17 104.944,65.17 108.254,61.86 107.826,61.432 105.653,61.432 104.096,62.989 93.661,62.989 93.524,62.852 93.481,62.852 93.481,62.288 93.311,62.118 91.156,62.118
"+5 IN" on Top Layer "+5_IN_L01_P024" (solid, pour order 24): 94.088,61.237 94.833,61.982 95.664,61.975 101.036,61.975 101.27,61.745 101.284,61.745 101.982,61.048 101.974,60.526 101.974,59.997 102.159,59.812 102.435,59.812 102.513,59.756 102.518,59.761 105.342,59.761 105.408,59.695 105.401,59.688 105.401,58.789 105.425,58.765 106.218,58.765 106.218,58.754 106.25,58.722 106.25,58.524 106.199,58.473 105.428,58.473 105.428,58.454 105.401,58.427 105.401,58.301 105.352,58.252 105.345,58.259 102.695,58.259 102.695,58.264 102.649,58.31 102.651,58.312 102.651,58.422 102.646,58.422 102.609,58.459 102.481,58.452 102.473,58.448 101.765,58.448 101.681,58.534 100.841,59.374 95.206,59.374 94.088,59.504
"+5 IN" on Top Layer "+5_IN_L01_P019" (solid, pour order 19): 90.735,61.019 90.912,61.02 94.085,61.02 94.085,61.014 94.159,60.933 94.614,60.478 94.614,59.171 94.405,58.962 93.646,58.962 93.633,58.975 93.617,58.959 93.612,54.098 93.11,53.596 93.11,50.176 92.784,49.85 92.47,49.85 92.47,50.334 91.084,51.72 91.084,51.755 90.47,52.369 90.399,52.369 90.399,58.315 90.414,58.33 90.414,60.698
+5 on Top Layer "+5_L01_P020" (solid, pour order 20): 118.472,56.045 118.859,56.432 118.859,60.475 118.543,60.791 118.535,60.783 117.971,60.761 116.176,60.761 116.176,60.76 115.831,60.415 115.831,57.976 113.082,55.227 113.082,52.502 113.139,52.502 115.336,50.305 115.693,50.305 115.731,50.308 115.731,50.41 115.828,50.507 115.818,50.517 115.818,51.376 115.164,52.03 115.164,54.871 116.338,56.045
GND on Top Layer "GND_L01_P022" (solid, pour order 22): 102.425,57.992 102.514,57.899 105.389,57.899 105.483,57.805 106.234,57.805 106.237,57.804 106.423,57.804 106.512,57.729 106.512,57.55 106.423,57.461 106.3,57.461 106.299,57.46 105.537,57.46 105.519,57.478 105.47,57.429 105.47,57.032 105.426,56.988 105.426,56.959 105.426,56.958 105.426,56.182 105.427,56.181 105.391,56.145 105.167,56.145 105.134,56.178 105.134,56.898 105.076,56.956 102.674,56.956 102.599,57.031 102.599,57.381 102.589,57.381 102.502,57.468 102.502,57.453 101.845,57.453 101.83,57.438 101.764,57.504 101.764,58.251 101.783,58.27 102.348,58.27 102.422,58.228 102.425,58.225
"+5 OUT" on Top Layer "+5_OUT_L01_P021" (solid, pour order 21): 104.031,59.961 104.108,59.961 104.279,59.961 105.453,59.961 105.571,59.843 105.571,59.062 105.672,58.934 106.354,58.934 106.418,58.87 110.023,58.87 110.023,58.813 110.259,58.577 110.259,56.94 110.487,56.701 112.57,56.701 112.816,56.905 112.816,60.752 112.376,61.192 111.098,61.192 110.424,61.986 103.516,61.986 102.556,61.533 102.569,60.149 102.569,60.015 102.623,59.961
+3V3 on Top Layer "+3V3_L01_P015" (solid, pour order 15): 108.36,67.564 108.369,67.572 108.367,67.737 108.547,67.917 109.234,67.917 109.602,68.285 109.602,70.093 109.52,70.175 109.52,70.207 108.506,70.207 108.498,70.199 108.383,70.314 108.351,70.314 108.351,71 108.334,71.017 108.465,71.148 108.465,71.189 110.371,71.238 110.551,71.058 110.551,66.6 110.11,66.159 108.621,66.159 108.604,66.142 108.391,66.355 108.383,66.355 108.383,67.541
GND on Bottom Layer "GND_L02_P028" (solid, pour order 28): 87.893,43.663 cw(c87.893,44.687) 87.169,43.963 cw(c87.411,44.205) 87.069,44.205 87.069,117.039 cw(c88.093,117.039) 87.369,117.763 cw(c87.611,117.522) 87.611,117.863 125.369,117.863 cw(c125.369,117.139) 125.881,117.651 125.969,117.563 cw(c125.728,117.322) 126.069,117.322 126.069,44.263 cw(c125.345,44.263) 125.857,43.751 125.769,43.663 125.269,43.663

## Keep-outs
Keep-Out Layer:
  lines w1: 126.469,117.105 ccw(c125.469,117.105) 125.469,118.105 87.469,118.105 ccw(c87.469,117.105) 86.469,117.105 86.469,44.367 ccw(c87.739,44.367) 87.739,43.097 125.469,43.113 ccw(c125.469,44.113) 126.469,44.113 126.469,117.363

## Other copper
Bottom Layer:
  pour cut-out: 91.318,65.194 91.318,65.188 90.832,64.702 90.832,62.421 90.854,62.421 91.029,62.246 93.455,62.246 93.527,62.318 93.527,62.86 93.533,62.86 93.664,62.991 104.097,62.991 104.097,62.97 105.622,61.445 107.838,61.445 107.838,61.45 108.269,61.881 104.956,65.193 104.881,65.193
  pour cut-out: 116.167,60.764 115.829,60.426 115.807,60.426 115.807,57.977 115.816,57.968 113.073,55.225 113.042,55.225 113.042,52.525 114.876,50.691 115.802,50.691 115.82,50.709 115.82,51.398 115.807,51.398 115.162,52.043 115.184,52.065 115.184,54.9 115.188,54.9 116.329,56.041 116.346,56.024 118.489,56.024 118.489,56.033 118.879,56.423 118.866,56.436 118.866,60.488 118.844,60.488 118.533,60.799
  pour cut-out: 103.561,61.993 103.079,61.787 102.537,61.538 102.552,61.523 102.552,60.021 102.628,59.945 102.639,59.956 105.472,59.956 105.472,59.945 105.578,59.839 105.567,59.828 105.567,59.027 105.673,58.921 105.688,58.936 106.36,58.936 106.36,58.933 106.432,58.861 106.447,58.876 110.019,58.876 110.019,58.816 110.27,58.565 110.27,56.91 110.484,56.696 112.612,56.696 112.612,56.74 112.819,56.947 112.819,60.768 112.376,61.211 111.112,61.211 111.112,61.263 110.373,62.002
  pour cut-out: 90.806,60.933 90.771,60.933 90.388,60.55 90.388,52.351 90.415,52.351 92.305,50.461 93.089,50.461 93.089,53.58 93.072,53.597 93.577,54.102 93.577,58.929 93.647,58.999 94.404,58.999 94.622,59.217 94.622,60.533 94.596,60.533 94.213,60.916
  pour cut-out: 95.64,61.987 94.43,61.128 94.079,60.909 94.079,59.644 94.309,59.414 100.78,59.414 101.772,58.422 101.808,58.458 102.608,58.458 102.65,58.416 102.638,58.404 102.638,58.282 102.681,58.282 102.723,58.24 105.362,58.24 105.41,58.288 105.404,58.294 105.404,58.446 105.434,58.476 105.435,58.475 106.21,58.475 106.259,58.524 106.254,58.529 106.254,58.739 106.212,58.781 105.428,58.781 105.428,58.799 105.396,58.831 105.396,59.706 105.391,59.706 105.337,59.76 102.469,59.76 102.412,59.817 102.407,59.812 102.143,59.812 102.143,59.817 101.975,59.985 101.98,59.99 101.98,61.041 101.057,61.964

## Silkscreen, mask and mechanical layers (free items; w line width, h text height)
Top Overlay:
  drawing of 38 lines, arcs and shapes, not listed
  text "IMU" at 95.373,111.709 h1.25
  text "Rev 1.2 /  / EE Capstone 2025-26 / Group 12" at 110.274,99.037 h1.25
  text "SDA" at 102.046,81.367 h1.25
  text "SCL" at 102.124,78.293 h1.25
  text "Direct" at 88.943,64.522 h1
  text "U2" at 103.621,61.395 h1.52
  text "With / E-fuse" at 87.175,57.308 h1
  text "To Pi" at 119.665,52.908 h1.25
  text "From / Battery" at 87.538,52.106 h1.25
Top Paste:
  region: 103.926,57.123 103.926,57.113 103.918,57.095 103.904,57.081 103.885,57.073 103.876,57.073 102.788,57.073 102.778,57.073 102.759,57.081 102.745,57.095 102.738,57.113 102.738,57.123 102.738,57.783 102.738,57.793 102.745,57.811 102.759,57.825 102.778,57.833 102.788,57.833 103.876,57.833 103.885,57.833 103.904,57.825 103.918,57.811 103.926,57.793 103.926,57.783
  region: 103.926,58.403 103.926,58.393 103.918,58.375 103.904,58.361 103.885,58.353 103.876,58.353 102.788,58.353 102.778,58.353 102.759,58.361 102.745,58.375 102.738,58.393 102.738,58.403 102.738,59.603 102.738,59.613 102.745,59.631 102.759,59.645 102.778,59.653 102.788,59.653 103.876,59.653 103.885,59.653 103.904,59.645 103.918,59.631 103.926,59.613 103.926,59.603
  region: 105.314,57.783 105.314,57.123 105.314,57.113 105.306,57.095 105.292,57.081 105.273,57.073 105.264,57.073 104.176,57.073 104.166,57.073 104.147,57.081 104.133,57.095 104.126,57.113 104.126,57.123 104.126,57.783 104.126,57.793 104.133,57.811 104.147,57.825 104.166,57.833 104.176,57.833 105.264,57.833 105.273,57.833 105.292,57.825 105.306,57.811 105.314,57.793 105.314,57.783
  region: 104.126,58.403 104.126,59.603 104.126,59.613 104.133,59.631 104.147,59.645 104.166,59.653 104.176,59.653 105.264,59.653 105.273,59.653 105.292,59.645 105.306,59.631 105.314,59.613 105.314,59.603 105.314,58.403 105.314,58.393 105.306,58.375 105.292,58.361 105.273,58.353 105.264,58.353 104.176,58.353 104.166,58.353 104.147,58.361 104.133,58.375 104.126,58.393 104.126,58.403
Mechanical 1:
  lines w0.254: 86.469,44.367 ccw(c87.739,44.367) 87.739,43.097 125.469,43.113 ccw(c125.469,44.113) 126.469,44.113 126.469,117.105 ccw(c125.469,117.105) 125.469,118.105 87.469,118.105 ccw(c87.34,117.234) 86.469,117.363 86.469,44.367
Top Assembly:
  lines w0.2: 101.726,56.078 101.726,60.678 106.326,60.678 106.326,56.078 101.726,56.078
Top 3D Body:
  lines w0.2: 101.976,56.328 101.976,60.428 106.076,60.428 106.076,56.328 101.976,56.328
Top Courtyard:
  lines w0.2: 101.726,56.078 101.726,60.678 106.326,60.678 106.326,56.078 101.726,56.078
Top Component Center:
  lines w0.1: 103.526,58.378 104.526,58.378 ; 104.026,57.878 104.026,58.878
